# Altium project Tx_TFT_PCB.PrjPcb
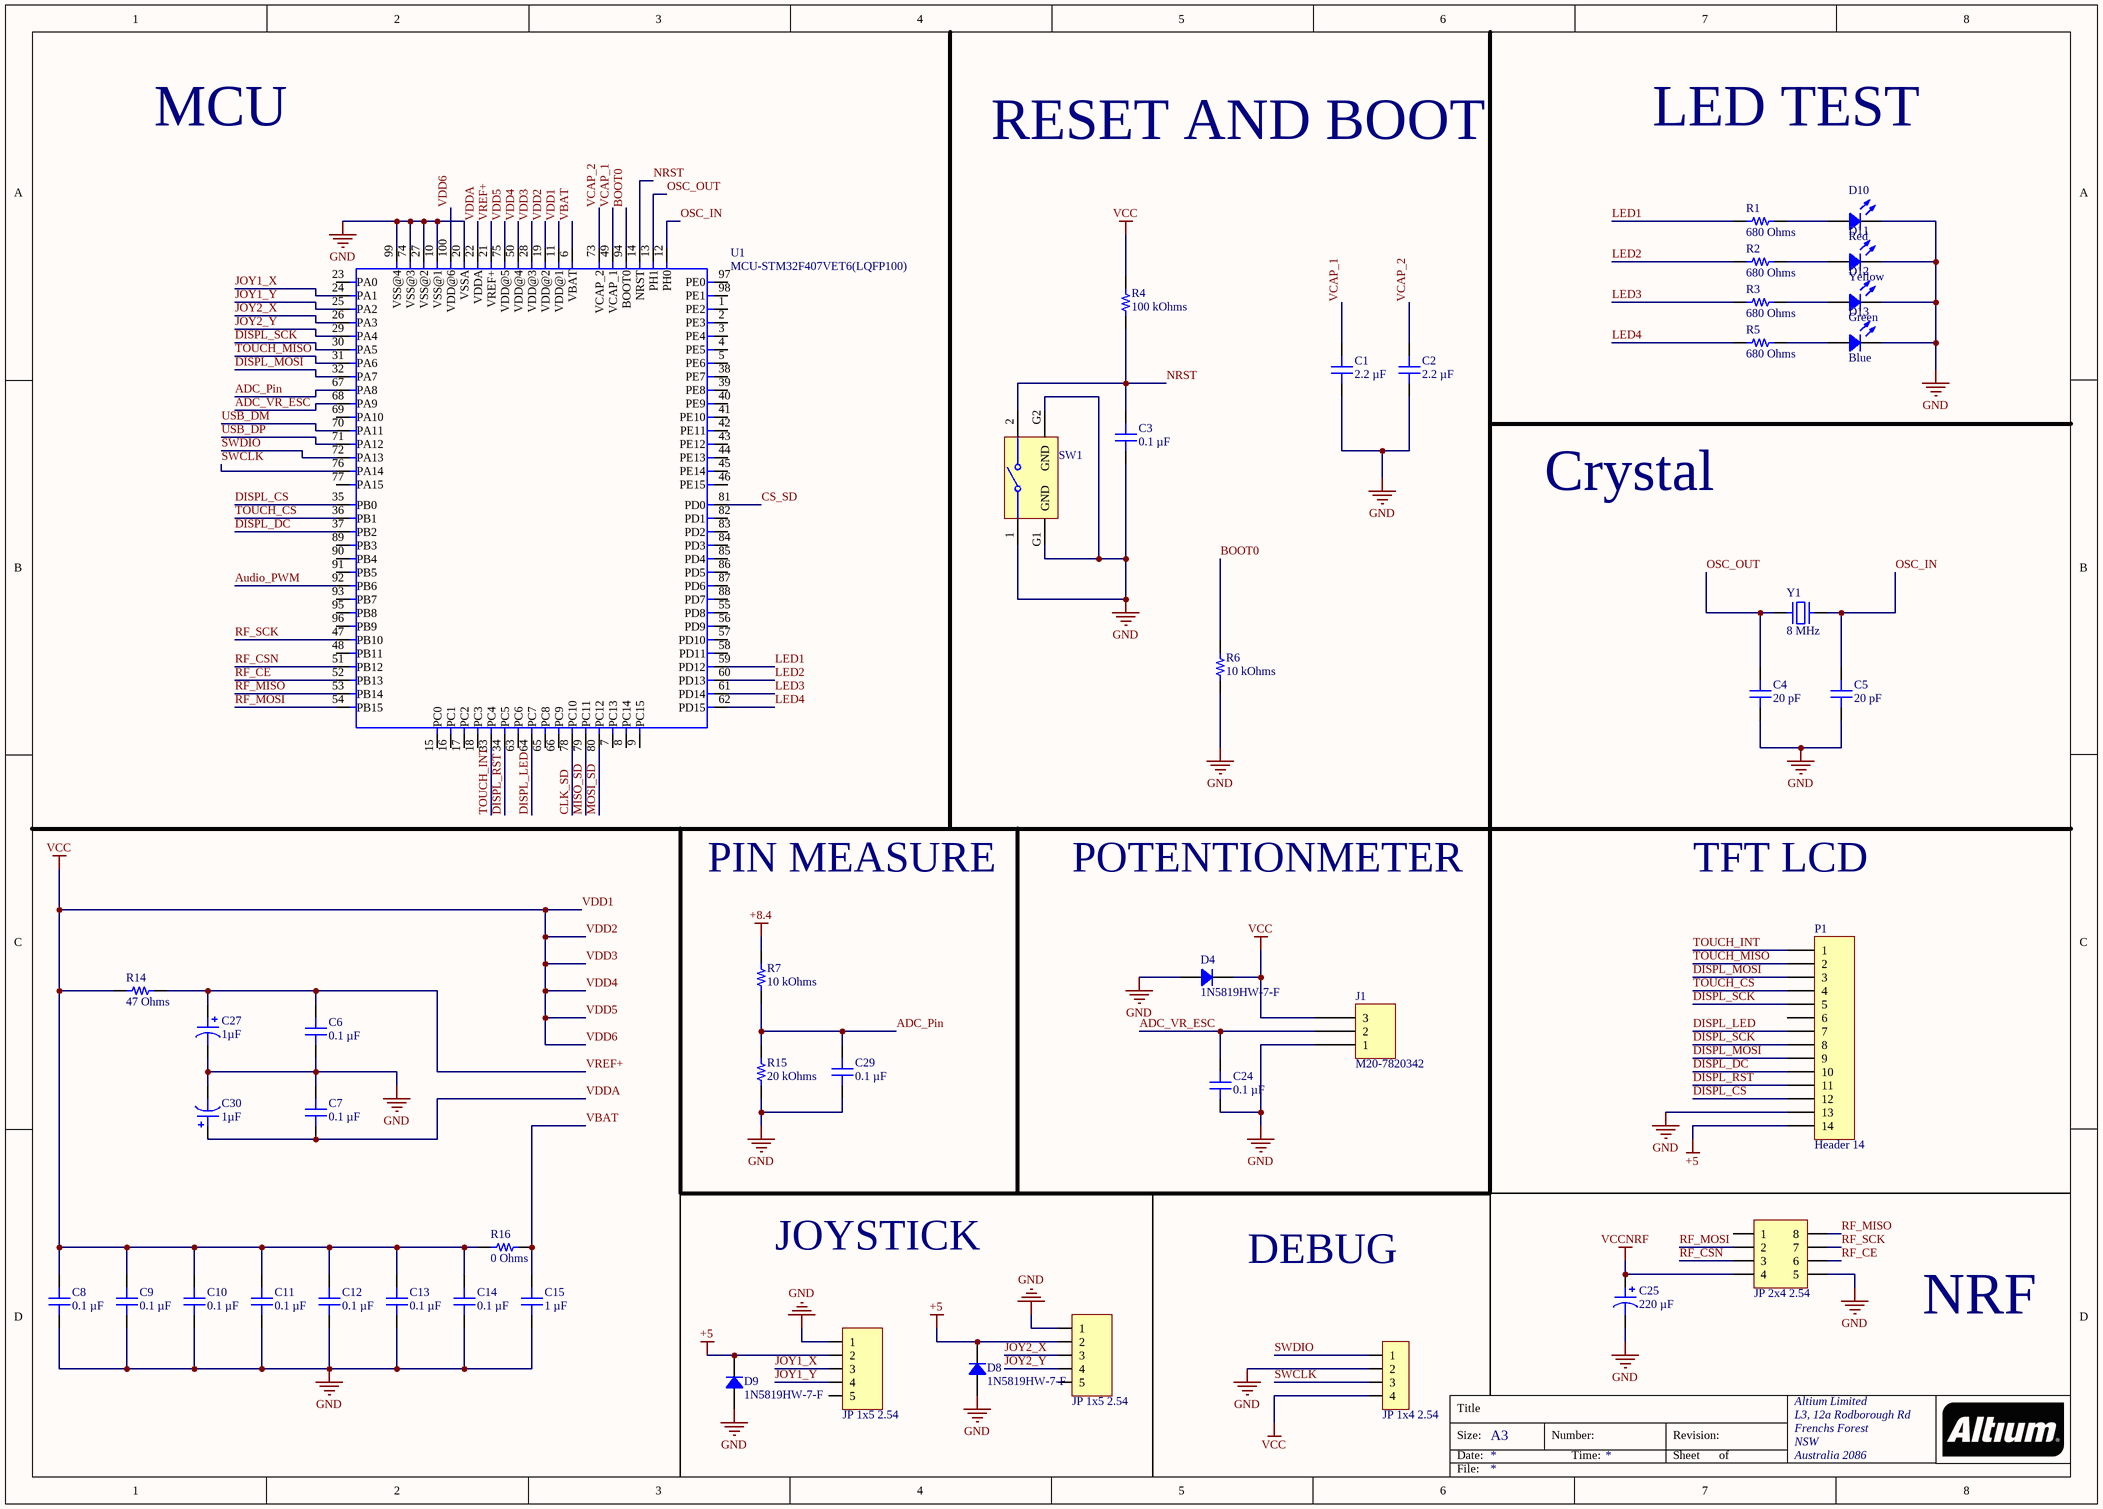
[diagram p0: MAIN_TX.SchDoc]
4 sheets, 123 parts. Net scope: global (net labels, ports and power ports of the same name join across sheets).
Board file: TX_PCB.PcbDoc
Sheets:
  MAIN_TX.SchDoc
  Audio.SchDoc
  Power_2.SchDoc
  USB_C.SchDoc

## Sheet MAIN_TX.SchDoc
size A3; Organization: Altium Limited; Address1: L3, 12a Rodborough Rd; Address2: Frenchs Forest; Address3: NSW; Address4: Australia 2086

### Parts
C1  2.2 µF  [CAP 0402_1005]
C2  2.2 µF  [CAP 0402_1005]
C3  0.1 µF  [CAP 0402_1005]
C4  20 pF  [CAP 0402_1005]
C5  20 pF  [CAP 0402_1005]
C6  0.1 µF  [CAP 0402_1005]
C7  0.1 µF  [CAP 0402_1005]
C8  0.1 µF  [CAP 0402_1005]
C9  0.1 µF  [CAP 0402_1005]
C10  0.1 µF  [CAP 0402_1005]
C11  0.1 µF  [CAP 0402_1005]
C12  0.1 µF  [CAP 0402_1005]
C13  0.1 µF  [CAP 0402_1005]
C14  0.1 µF  [CAP 0402_1005]
C15  1 µF  [CAP 0402_1005]
C24  0.1 µF  [CAP 0603_1608]
C25  220 µF  [CAP ALSMD 6.6MM H6.1MM]
C27  1µF  [CAP POL 1206_3216]
C29  0.1 µF  [CAP 0603_1608]
C30  1µF  [CAP POL 1206_3216]
D4  1N5819HW-7-F  [SOD-123]
D8  1N5819HW-7-F  [SOD-123]
D9  1N5819HW-7-F  [SOD-123]
D10  Red  [LED 0402_1005 RED]
D11  Yellow  [LED 0402_1005 YELLOW]
D12  Green  [LED 0402_1005 GREEN]
D13  Blue  [LED 0402_1005 BLUE]
J1  M20-7820342  [HARWIN M20-7820345]
JP1  JP 1x4 2.54  [JP 1x4 CC]
JP2  JP 2x4 2.54  [JP 2x4 CT]
JP3  JP 1x5 2.54  [JP 1x5 DT]
JP4  JP 1x5 2.54  [JP 1x5 DT]
P1  Header 14  [HDR1X14]
R1  680 Ohms  [RES 0402_1005]
R2  680 Ohms  [RES 0402_1005]
R3  680 Ohms  [RES 0402_1005]
R4  100 kOhms  [RES 0402_1005]
R5  680 Ohms  [RES 0402_1005]
R6  10 kOhms  [RES 0402_1005]
R7  10 kOhms  [RES 0402_1005]
R14  47 Ohms  [RES 0603_1608]
R15  20 kOhms  [RES 0603_1608]
R16  0 Ohms  [RES 0603_1608]
SW1  431256083716  [4312560837x6]  (value not drawn)
U1  MCU-STM32F407VET6(LQFP100)  [LQFP100-0.5-13.8X13.8MM]
Y1  8 MHz  [NDK NX5032GA]

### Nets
+5: D8.2 D9.2 JP3.2 JP4.2 P1.14
+8.4: R7.2
GND: C1.1 C2.1 C3.1 C4.1 C5.1 C6.1 C7.2 C8.1 C9.1 C10.1 C11.1 C12.1 C13.1 C14.1 C15.1 C24.1 C25.2 C27.2 C29.1 C30.2 D4.1 D8.1 D9.1 D10.2 D11.2 D12.2 D13.2 J1.1 JP1.2 JP2.5 JP3.1 JP4.1 P1.13 R6.1 R15.1 SW1.1 SW1.G1(GND) SW1.G2(GND) U1.10(VSS@1) U1.20(VSSA) U1.27(VSS@2) U1.74(VSS@3) U1.99(VSS@4)
VCCNRF: C25.1 JP2.4
VDD1: C8.2 C9.2 C10.2 C11.2 C12.2 C13.2 C14.2 D4.2 J1.3 JP1.4 R4.2 R14.1 R16.1 U1.11(VDD@1) U1.19(VDD@2) U1.28(VDD@3) U1.50(VDD@4) U1.75(VDD@5) U1.100(VDD@6)  [also labelled VCC, VDD2, VDD3, VDD4, VDD5, VDD6]
ADC_Pin: C29.2 R7.1 R15.2 U1.67(PA8)
ADC_VR_ESC: C24.2 J1.2 U1.68(PA9)
Audio_PWM: U1.92(PB6)
BOOT0: R6.2 U1.94(BOOT0)
CLK_SD: U1.78(PC10)
CS_SD: U1.81(PD0)
DISPL_CS: P1.12 U1.35(PB0)
DISPL_DC: P1.10 U1.37(PB2)
DISPL_LED: P1.7 U1.64(PC7)
DISPL_MOSI: P1.3 P1.9 U1.32(PA7)
DISPL_RST: P1.11 U1.34(PC5)
DISPL_SCK: P1.5 P1.8 U1.30(PA5)
JOY1_X: JP3.3 U1.24(PA1)
JOY1_Y: JP3.4 U1.25(PA2)
JOY2_X: JP4.3 U1.26(PA3)
JOY2_Y: JP4.4 U1.29(PA4)
LED1: R1.1 U1.59(PD12)
LED2: R2.1 U1.60(PD13)
LED3: R3.1 U1.61(PD14)
LED4: R5.1 U1.62(PD15)
MISO_SD: U1.79(PC11)
MOSI_SD: U1.80(PC12)
NRST: C3.2 R4.1 SW1.2 U1.14(NRST)
OSC_IN: C5.2 U1.12(PH0) Y1.2
OSC_OUT: C4.2 U1.13(PH1) Y1.1
RF_CE: JP2.6 U1.52(PB13)
RF_CSN: JP2.3 U1.51(PB12)
RF_MISO: JP2.8 U1.53(PB14)
RF_MOSI: JP2.2 U1.54(PB15)
RF_SCK: JP2.7 U1.47(PB10)
SWCLK: JP1.3 U1.76(PA14)
SWDIO: JP1.1 U1.72(PA13)
TOUCH_CS: P1.4 U1.36(PB1)
TOUCH_INT: P1.1 U1.33(PC4)
TOUCH_MISO: P1.2 U1.31(PA6)
USB_DM: U1.70(PA11)
USB_DP: U1.71(PA12)
VBAT: C15.2 R16.2 U1.6(VBAT)
VCAP_1: C1.2 U1.49(VCAP_1)
VCAP_2: C2.2 U1.73(VCAP_2)
VDDA: C7.1 C30.1 U1.22(VDDA)
VREF+: C6.2 C27.1 R14.2 U1.21(VREF+)
NetD10_1: D10.1 R1.2
NetD11_1: D11.1 R2.2
NetD12_1: D12.1 R3.2
NetD13_1: D13.1 R5.2

Not connected (* = marked no-connect by the designer): JP2 1; JP3 5; JP4 5; P1 6; U1 1(PE2) 2(PE3) 3(PE4) 4(PE5) 5(PE6) 7(PC13) 8(PC14) 9(PC15) 15(PC0) 16(PC1) 17(PC2) 18(PC3) 23(PA0) 38(PE7) 39(PE8) 40(PE9) 41(PE10) 42(PE11) 43(PE12) 44(PE13) 45(PE14) 46(PE15) 48(PB11) 55(PD8) 56(PD9) 57(PD10) 58(PD11) 63(PC6) 65(PC8) 66(PC9) 69(PA10) 77(PA15) 82(PD1) 83(PD2) 84(PD3) 85(PD4) 86(PD5) 87(PD6) 88(PD7) 89(PB3) 90(PB4) 91(PB5) 93(PB7) 95(PB8) 96(PB9) 97(PE0) 98(PE1)

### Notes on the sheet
- MCU
- RESET AND BOOT
- LED TEST
- Crystal
- PIN MEASURE
- POTENTIONMETER
- TFT LCD
- JOYSTICK
- DEBUG
- NRF

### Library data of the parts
C1 C2 = GRT155C81A225KE13D: CAP CER 2.2UF 10V X6S 0402; manufacturer: Murata Electronics; Tolerance: ±10%
C3 C6-C14 = KGM05AR51A104KN: CAP CER 0.1UF 10V X5R 0402; manufacturer: KYOCERA AVX; Tolerance: ±10%
C4 C5 = C0402C200K8GAC7867: CAP CER 20PF 10V NP0 0402; manufacturer: KEMET; Temperature Coefficient: C0G, NP0; Tolerance: ±10%
C15 = GRM155C71A105KE11D: CAP CER 1UF 10V X7S 0402; manufacturer: Murata Electronics; Tolerance: ±10%
C24 C29 = VJ0603Y104KXQCW1BC: CAP CER 0.1UF 10V X7R 0603; manufacturer: Vishay Vitramon; Tolerance: ±10%
C25 = UCM1A221MCL1GS: CAP ALUM 220UF 20% 10V SMD; manufacturer: Nichicon; Impedance: 260 mOhms; Lifetime @ Temp.: 2000 Hrs @ 105°C; Polarization: Polar; Ripple Current @ High Frequency: 300 mA @ 100 kHz; Ripple Current @ Low Frequency: 150 mA @ 120 Hz; Surface Mount Land Size: 0.260" L x 0.260" W (6.60mm x 6.60mm)
C27 C30 = TAJA105K016RNJ: CAP TANT 1UF 10% 16V 1206; manufacturer: AVX Corporation; Manufacturer Size Code: A; ESR (Equivalent Series Resistance): 11Ohm; Type: Molded
D4 D8 D9 = 1N5819HW-7-F: DIODE SCHOTTKY 40V 1A SOD123; Manufacturer: Diodes Incorporated; Capacitance @ Vr, F: 60pF @ 4V, 1MHz; Current - Reverse Leakage @ Vr: 1 mA @ 40 V; Speed: Fast Recovery =< 500ns, > 200mA (Io); Voltage - Forward (Vf) (Max) @ If: 450 mV @ 1 A
D10 = SM0402RC: LED RED CLEAR 0402 SMD; Manufacturer: Bivar Inc.; Configuration: 0402; Current - Test: 20mA; Lens Color: Colorless; Lens Size: 0.50mm x 1.00mm; Lens Style: Rectangle with Flat Top; Millicandela Rating: 90mcd; Viewing Angle: 130°; Voltage - Forward (Vf) (Typ): 2.1V; Wavelength - Dominant: 631nm; Wavelength - Peak: 645nm
D11 = IN-S42ATY: LED YELLOW CLEAR 0402 SMD; Manufacturer: Inolux; Configuration: Standard; Current - Test: 20mA; Lens Size: 0.60mm x 0.45mm; Lens Style: Rectangle with Flat Top; Millicandela Rating: 145mcd; Viewing Angle: 130°; Voltage - Forward (Vf) (Typ): 1.9V; Wavelength - Dominant: 592nm; Wavelength - Peak: 593nm
D12 = APG1005ZGC-5MAV: LED GREEN CLEAR 0402 SMD; Manufacturer: Kingbright; Configuration: Standard; Current - Test: 5mA; Lens Color: Colorless; Lens Size: 0.60mm x 0.50mm; Lens Style: Rectangle with Flat Top; Millicandela Rating: 280mcd; Viewing Angle: 140°; Voltage - Forward (Vf) (Typ): 2.85V; Wavelength - Dominant: 525nm; Wavelength - Peak: 515nm
D13 = XZBBR68W5MAV-3: LED BLUE CLEAR 0402 SMD; Manufacturer: SunLED; Configuration: Standard; Current - Test: 5mA; Lens Color: Colorless; Lens Size: 0.60mm x 0.50mm; Lens Style: Rectangle with Flat Top; Millicandela Rating: 27mcd; Viewing Angle: 140°; Voltage - Forward (Vf) (Typ): 2.9V; Wavelength - Dominant: 467nm; Wavelength - Peak: 461nm
J1 = M20-7820342: CONN RCPT 3POS 0.1 GOLD PCB; Manufacturer: Harwin Inc.; Connector Type: Receptacle; Contact Length - Post: 0.118" (3.00mm); Current Rating (Amps): 3A; Mated Stacking Heights: 11.04mm, 12.63mm; Material Flammability Rating: UL94 V-0; Number of Positions: 3; Number of Positions Loaded: All; Pitch - Mating: 0.100" (2.54mm); Style: Board to Board or Cable
JP1 = JP 1x4 2.54 Cai Cong: Cắm; Ten_Linh_Kien: Jump Đơn Cái 2.54MM 1x40P Cong; Don_Vi: Con; Ma_Hang: MH001265
JP2 = JP 2x4 2.54 Cai Thang: Cắm; Ten_Linh_Kien: Jump Đôi Cái 2.54MM 2x20P Thẳng; Don_Vi: Con; Ma_Hang: MH008647
JP3 JP4 = JP 1x5 2.54 Duc Thang: Cắm; Ten_Linh_Kien: Jump Đơn Đực 2.54MM 1x40P Thẳng 11MM; Don_Vi: Con; Ma_Hang: MH000903
P1 = Header 14: Header, 14-Pin
R1-R3 R5 = RC0402FR-07680RL: RES 680 OHM 1% 1/16W 0402; Manufacturer: Yageo; Power (Watts): 0.063W, 1/16W; Temperature Coefficient: ±100ppm/°C
R4 = MCS04020D1003BE100: RES SMD 100K OHM 0.1% 1/16W 0402; Manufacturer: Vishay Beyschlag; Power (Watts): 0.063W, 1/16W; Temperature Coefficient: ±25ppm/°C
R6 R7 = RP73PF1E10KBTD: RES 10K OHM 0.1% 1/10W 0402; Manufacturer: TE Connectivity Passive Product; Power (Watts): 0.1W, 1/10W; Temperature Coefficient: ±25ppm/°C
R14 = CRT0603-FY-47R0ELF: RES SMD 47 OHM 1% 1/10W 0603; Manufacturer: Bourns Inc.; Power (Watts): 0.1W, 1/10W; Temperature Coefficient: ±25ppm/°C
R15 = RG1608P-203-B-T5: RES SMD 20K OHM 0.1% 1/10W 0603; Manufacturer: Susumu; Power (Watts): 0.1W, 1/10W; Temperature Coefficient: ±25ppm/°C
R16 = CR0603AJ/-000ELF: RES 0 OHM JUMPER 1/10W 0603; Manufacturer: Bourns Inc.; Power (Watts): 0.1W, 1/10W
SW1 = 431256083716: WS-TATU THT Tact Switch 6x6mm Right Angled Type with ground terminal, SPST-NO, 12VDC, 50mA, 160g; Manufacturer: Wurth Elektronik; Washable: No
U1 = MCU-STM32F407VET6(LQFP100): ARMÂ® CortexÂ®-M4 STM32F4 Microcontroller IC 32-Bit Single-Core 168MHz 512KB (512K x 8) FLASH 100-LQFP (14x14); MF: STMicroelectronics
Y1 = NX5032GA-8.000M-STD-CSU-1: CRYSTAL 8.0000MHZ 8PF SMD; Manufacturer: NDK America, Inc.; ESR (Equivalent Series Resistance): 300 Ohms; Frequency Stability: ±150ppm; Frequency Tolerance: ±50ppm; Operating Mode: Fundamental

## Sheet Audio.SchDoc
size A4; Organization: Altium Limited; Address1: L3, 12a Rodborough Rd; Address2: Frenchs Forest; Address3: NSW; Address4: Australia 2086
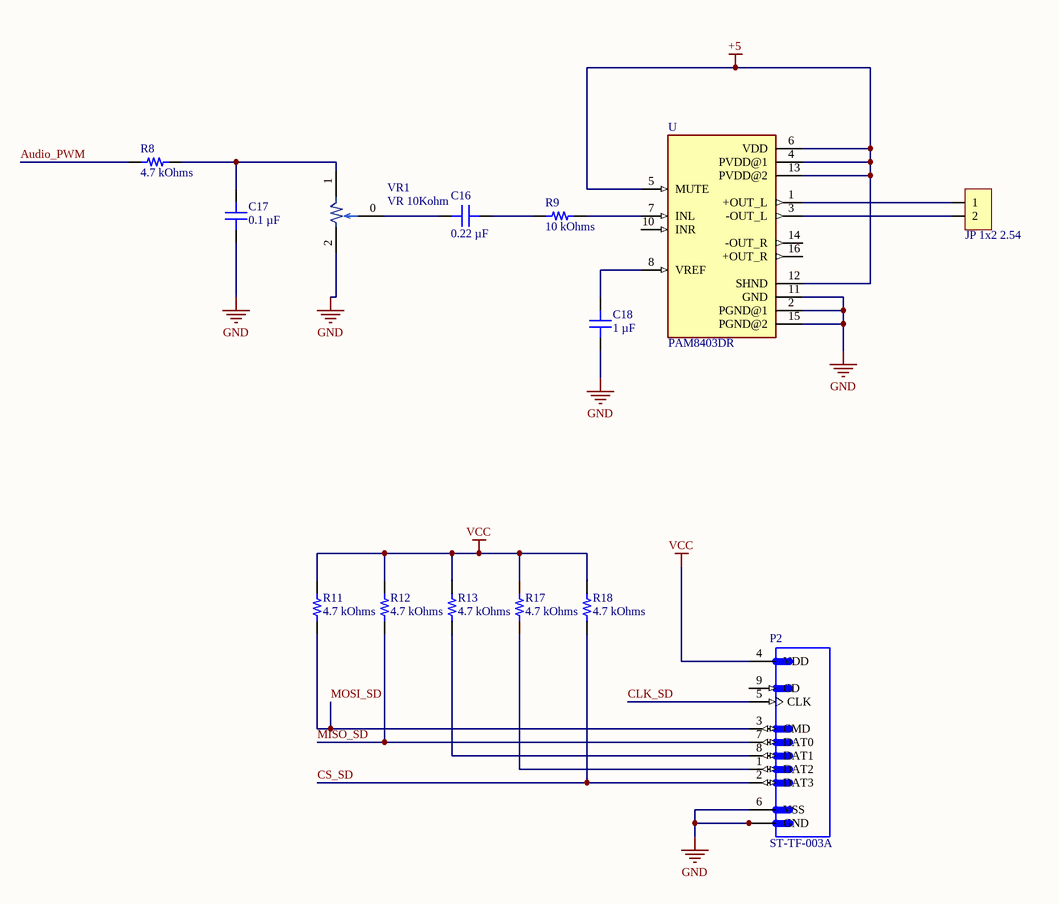
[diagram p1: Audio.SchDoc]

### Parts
C16  0.22 µF  [CAP 0402_1005]
C17  0.1 µF  [CAP 0402_1005]
C18  1 µF  [CAP 0402_1005]
JP5  JP 1x2 2.54  [JP 1x2 CT]
P2  ST-TF-003A  [SUNTECH_ST-TF-003A]
R8  4.7 kOhms  [RES 0402_1005]
R9  10 kOhms  [RES 0402_1005]
R11  4.7 kOhms  [RES 0402_1005]
R12  4.7 kOhms  [RES 0402_1005]
R13  4.7 kOhms  [RES 0402_1005]
R17  4.7 kOhms  [RES 0402_1005]
R18  4.7 kOhms  [RES 0402_1005]
U  PAM8403DR  [SOIC127P605X150-16N]
VR1  VR 10Kohm  [VR 10kohm]

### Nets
+5: U.4(PVDD@1) U.5(MUTE) U.6(VDD) U.12(SHND) U.13(PVDD@2)
GND: C17.1 C18.1 P2.6(VSS) P2.G1(GND) P2.G2(GND) P2.G3(GND) P2.G4(GND) U.2(PGND@1) U.11(GND) U.15(PGND@2) VR1.2
VCC: P2.4(VDD) R11.2 R12.2 R13.2 R17.2 R18.2  [project net VDD1]
Audio_PWM: R8.2
CLK_SD: P2.5(CLK)
CS_SD: P2.2(DAT3) R18.1
MISO_SD: P2.7(DAT0) R12.1
MOSI_SD: P2.3(CMD) R11.1
NetC16_1: C16.1 VR1.0
NetC16_2: C16.2 R9.1
NetC17_2: C17.2 R8.1 VR1.1
NetC18_2: C18.2 U.8(VREF)
NetJP5_1: JP5.1 U.1(+OUT_L)
NetJP5_2: JP5.2 U.3(-OUT_L)
NetP2_1: P2.1(DAT2) R17.1
NetP2_8: P2.8(DAT1) R13.1
NetR9_2: R9.2 U.7(INL)

Not connected (* = marked no-connect by the designer): P2 9(CD); U 10(INR) 14(-OUT_R) 16(+OUT_R)

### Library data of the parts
C16 = 0402X224K100CT: CAP CER 0.22UF 10V X5R 0402; manufacturer: Walsin Technology Corporation; Tolerance: ±10%
C17 = CGA2B2X5R1A104M050BA: CAP CER 0.1UF 10V X5R 0402; manufacturer: TDK Corporation; Tolerance: ±20%
C18 = C0402C105K8PAC7867: CAP CER 1UF 10V X5R 0402; manufacturer: KEMET; Tolerance: ±10%
JP5 = JP 1x2 2.54 Cai Thang: Cắm; Ten_Linh_Kien: Jump Đơn Cái 2.54MM 1x20P Thẳng; Don_Vi: Con; Ma_Hang: MH004006
P2 = ST-TF-003A: Micro SD Card Socket
R8 R11-R13 R17 R18 = RK73H1ERTTP4701F: RES 4.7K OHM 1% 1/10W 0402; Manufacturer: KOA Speer Electronics, Inc.; Power (Watts): 0.1W, 1/10W; Temperature Coefficient: ±100ppm/°C
R9 = MCS0402MC1002FE000: RES SMD 10K OHM 1% 1/10W 0402; Manufacturer: Vishay Beyschlag; Power (Watts): 0.1W, 1/10W; Temperature Coefficient: ±50ppm/°C
U = PAM8403DR: Amplifier IC 2-Channel _Stereo_ Class D 16-SOP; MF: Diodes Inc.

## Sheet Power_2.SchDoc
size A4; Organization: Altium Limited; Address1: L3, 12a Rodborough Rd; Address2: Frenchs Forest; Address3: NSW; Address4: Australia 2086
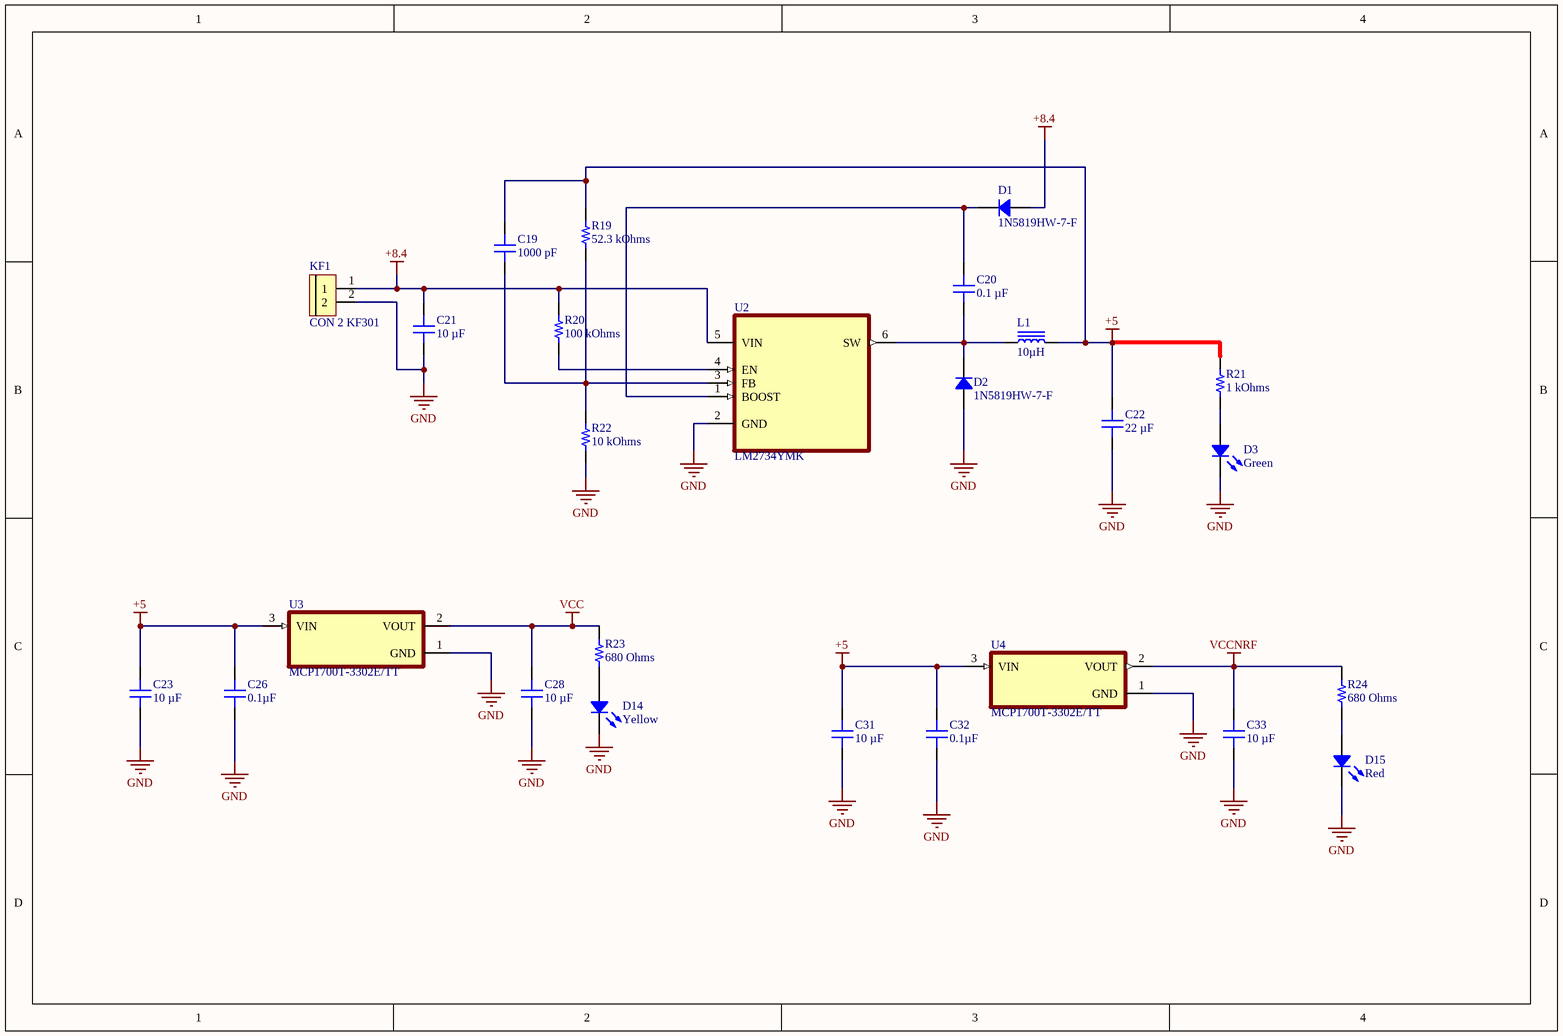
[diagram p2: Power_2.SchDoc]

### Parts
C19  1000 pF  [CAP 0402_1005]
C20  0.1 µF  [CAP 0402_1005]
C21  10 µF  [CAP 1210_3225 - 1MM]
C22  22 µF  [CAP 1210_3225 - 1MM]
C23  10 µF  [CAP 1210_3225 - 1MM]
C26  0.1µF  [CAP 0402_1005]
C28  10 µF  [CAP 1210_3225 - 1MM]
C31  10 µF  [CAP 1210_3225 - 1MM]
C32  0.1µF  [CAP 0402_1005]
C33  10 µF  [CAP 1210_3225 - 1MM]
D1  1N5819HW-7-F  [SOD-123]
D2  1N5819HW-7-F  [SOD-123]
D3  Green  [LED 0402_1005 GREEN]
D14  Yellow  [LED 0402_1005 YELLOW]
D15  Red  [LED 0402_1005 RED]
KF1  CON 2 KF301  [Con 2 KF301 5.08]
L1  10µH  [TDK SLF7032]
R19  52.3 kOhms  [RES 0402_1005]
R20  100 kOhms  [RES 0402_1005]
R21  1 kOhms  [RES 0402_1005]
R22  10 kOhms  [RES 0402_1005]
R23  680 Ohms  [RES 0402_1005]
R24  680 Ohms  [RES 0402_1005]
U2  LM2734YMK  [SOT95P285X100-6N]
U3  MCP1700T-3302E/TT  [SOT95P237X112-3N]
U4  MCP1700T-3302E/TT  [SOT95P237X112-3N]

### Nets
+5: C19.2 C22.2 C23.2 C26.2 C31.2 C32.2 L1.2 R19.2 R21.2 U3.3(VIN) U4.3(VIN)
+8.4: C21.2 D1.1 KF1.1 R20.2 U2.5(VIN)
GND: C21.1 C22.1 C23.1 C26.1 C28.1 C31.1 C32.1 C33.1 D2.1 D3.2 D14.2 D15.2 KF1.2 R22.1 U2.2(GND) U3.1(GND) U4.1(GND)
VCC: C28.2 R23.2 U3.2(VOUT)  [project net VDD1]
VCCNRF: C33.2 R24.2 U4.2(VOUT)
NetC19_1: C19.1 R19.1 R22.2 U2.3(FB)
NetC20_1: C20.1 D2.2 L1.1 U2.6(SW)
NetC20_2: C20.2 D1.2 U2.1(BOOST)
NetD3_1: D3.1 R21.1
NetD14_1: D14.1 R23.1
NetD15_1: D15.1 R24.1
NetR20_1: R20.1 U2.4(EN)

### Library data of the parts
C19 = LMF105B7102MVHF: CAP CER 1000PF 10V X7R 0402; manufacturer: Taiyo Yuden; Tolerance: ±20%
C20 = KGM05AR51A104KN: as C3 on sheet MAIN_TX
C21 C23 C28 C31 C33 = CGA6P3X8R1C106M250AB: CAP CER 10UF 16V X8R 1210; manufacturer: TDK Corporation; Tolerance: ±20%
C22 = C1210C226K4RAC7800: CAP CER 22UF 16V X7R 1210; manufacturer: KEMET; Tolerance: ±10%
C26 C32 = 0402ZC104KAT2A: CAP CER 0.1UF 10V X7R 0402; manufacturer: AVX Corporation; Tolerance: ±10%
D1 D2 = 1N5819HW-7-F: as D4 on sheet MAIN_TX
D3 = QBLP595-AG15-2897: LED GREEN CLEAR 0402 SMD; Manufacturer: QT Brightek (QTB); Configuration: Standard; Current - Test: 5mA; Lens Color: Colorless; Lens Size: 0.70mm x 0.50mm; Lens Style: Rectangle with Flat Top; Millicandela Rating: 16.5mcd; Viewing Angle: 140°; Voltage - Forward (Vf) (Typ): 1.9V; Wavelength - Dominant: 570nm
D14 = IN-S42BT5Y: LED YELLOW CLEAR 0402 SMD; Manufacturer: Inolux; Configuration: 0402; Current - Test: 5mA; Lens Color: 0.50mm; Lens Size: 0.70mm x 0.50mm; Lens Style: Rectangle with Flat Top; Millicandela Rating: 23mcd; Viewing Angle: 120°; Voltage - Forward (Vf) (Typ): 2V; Wavelength - Dominant: 585nm; Wavelength - Peak: 592nm
D15 = QBLP595-R5: LED RED CLEAR 0402 SMD; Manufacturer: QT Brightek (QTB); Configuration: Standard; Current - Test: 5mA; Lens Color: Colorless; Lens Size: 0.70mm x 0.50mm; Lens Style: Rectangle with Flat Top; Millicandela Rating: 31.5mcd; Viewing Angle: 140°; Voltage - Forward (Vf) (Typ): 1.85V; Wavelength - Dominant: 620nm
KF1 = CON 2 KF301: Cắm; Ma_Hang: MH000987; Ten_Linh_Kien: CON 2 KF301-2P 5.08MM Xanh Dương
L1 = SLF7032T-100M1R4-2PF: FIXED IND 10UH 1.4A 63.6 MOHM; Manufacturer: TDK Corporation; DC Resistance (DCR): 63.6mOhm Max; Inductance Frequency - Test: 100kHz; Material - Core: Ferrite; Shielding: Shielded; Tolerance: ±20%; Type: Wirewound
R19 = ERJ-2RKF5232X: RES SMD 52.3K OHM 1% 1/10W 0402; Manufacturer: Panasonic Electronic Components; Power (Watts): 0.1W, 1/10W; Temperature Coefficient: ±100ppm/°C
R20 = RP73PF1E100KBTD: RES 100K OHM 0.1% 1/10W 0402; Manufacturer: TE Connectivity Passive Product; Power (Watts): 0.1W, 1/10W; Temperature Coefficient: ±25ppm/°C
R21 = MCS0402MC1001FE000: RES SMD 1K OHM 1% 1/10W 0402; Manufacturer: Vishay Beyschlag; Power (Watts): 0.1W, 1/10W; Temperature Coefficient: ±50ppm/°C
R22 = MCS0402MC1002FE000: as R9 on sheet Audio
R23 R24 = RC0402FR-07680RL: as R1 on sheet MAIN_TX
U2 = LM2734YMK: Buck Switching Regulator IC Positive Adjustable 0.8V 1 Output 1A SOT-23-6 Thin, TSOT-23-6; MF: Texas Instruments
U3 U4 = MCP1700T-3302E/TT: Linear Voltage Regulator IC 1 Output 250mA SOT-23-3; MF: Microchip

## Sheet USB_C.SchDoc
size A3; Organization: Altium Limited; Address1: L3, 12a Rodborough Rd; Address2: Frenchs Forest; Address3: NSW; Address4: Australia 2086
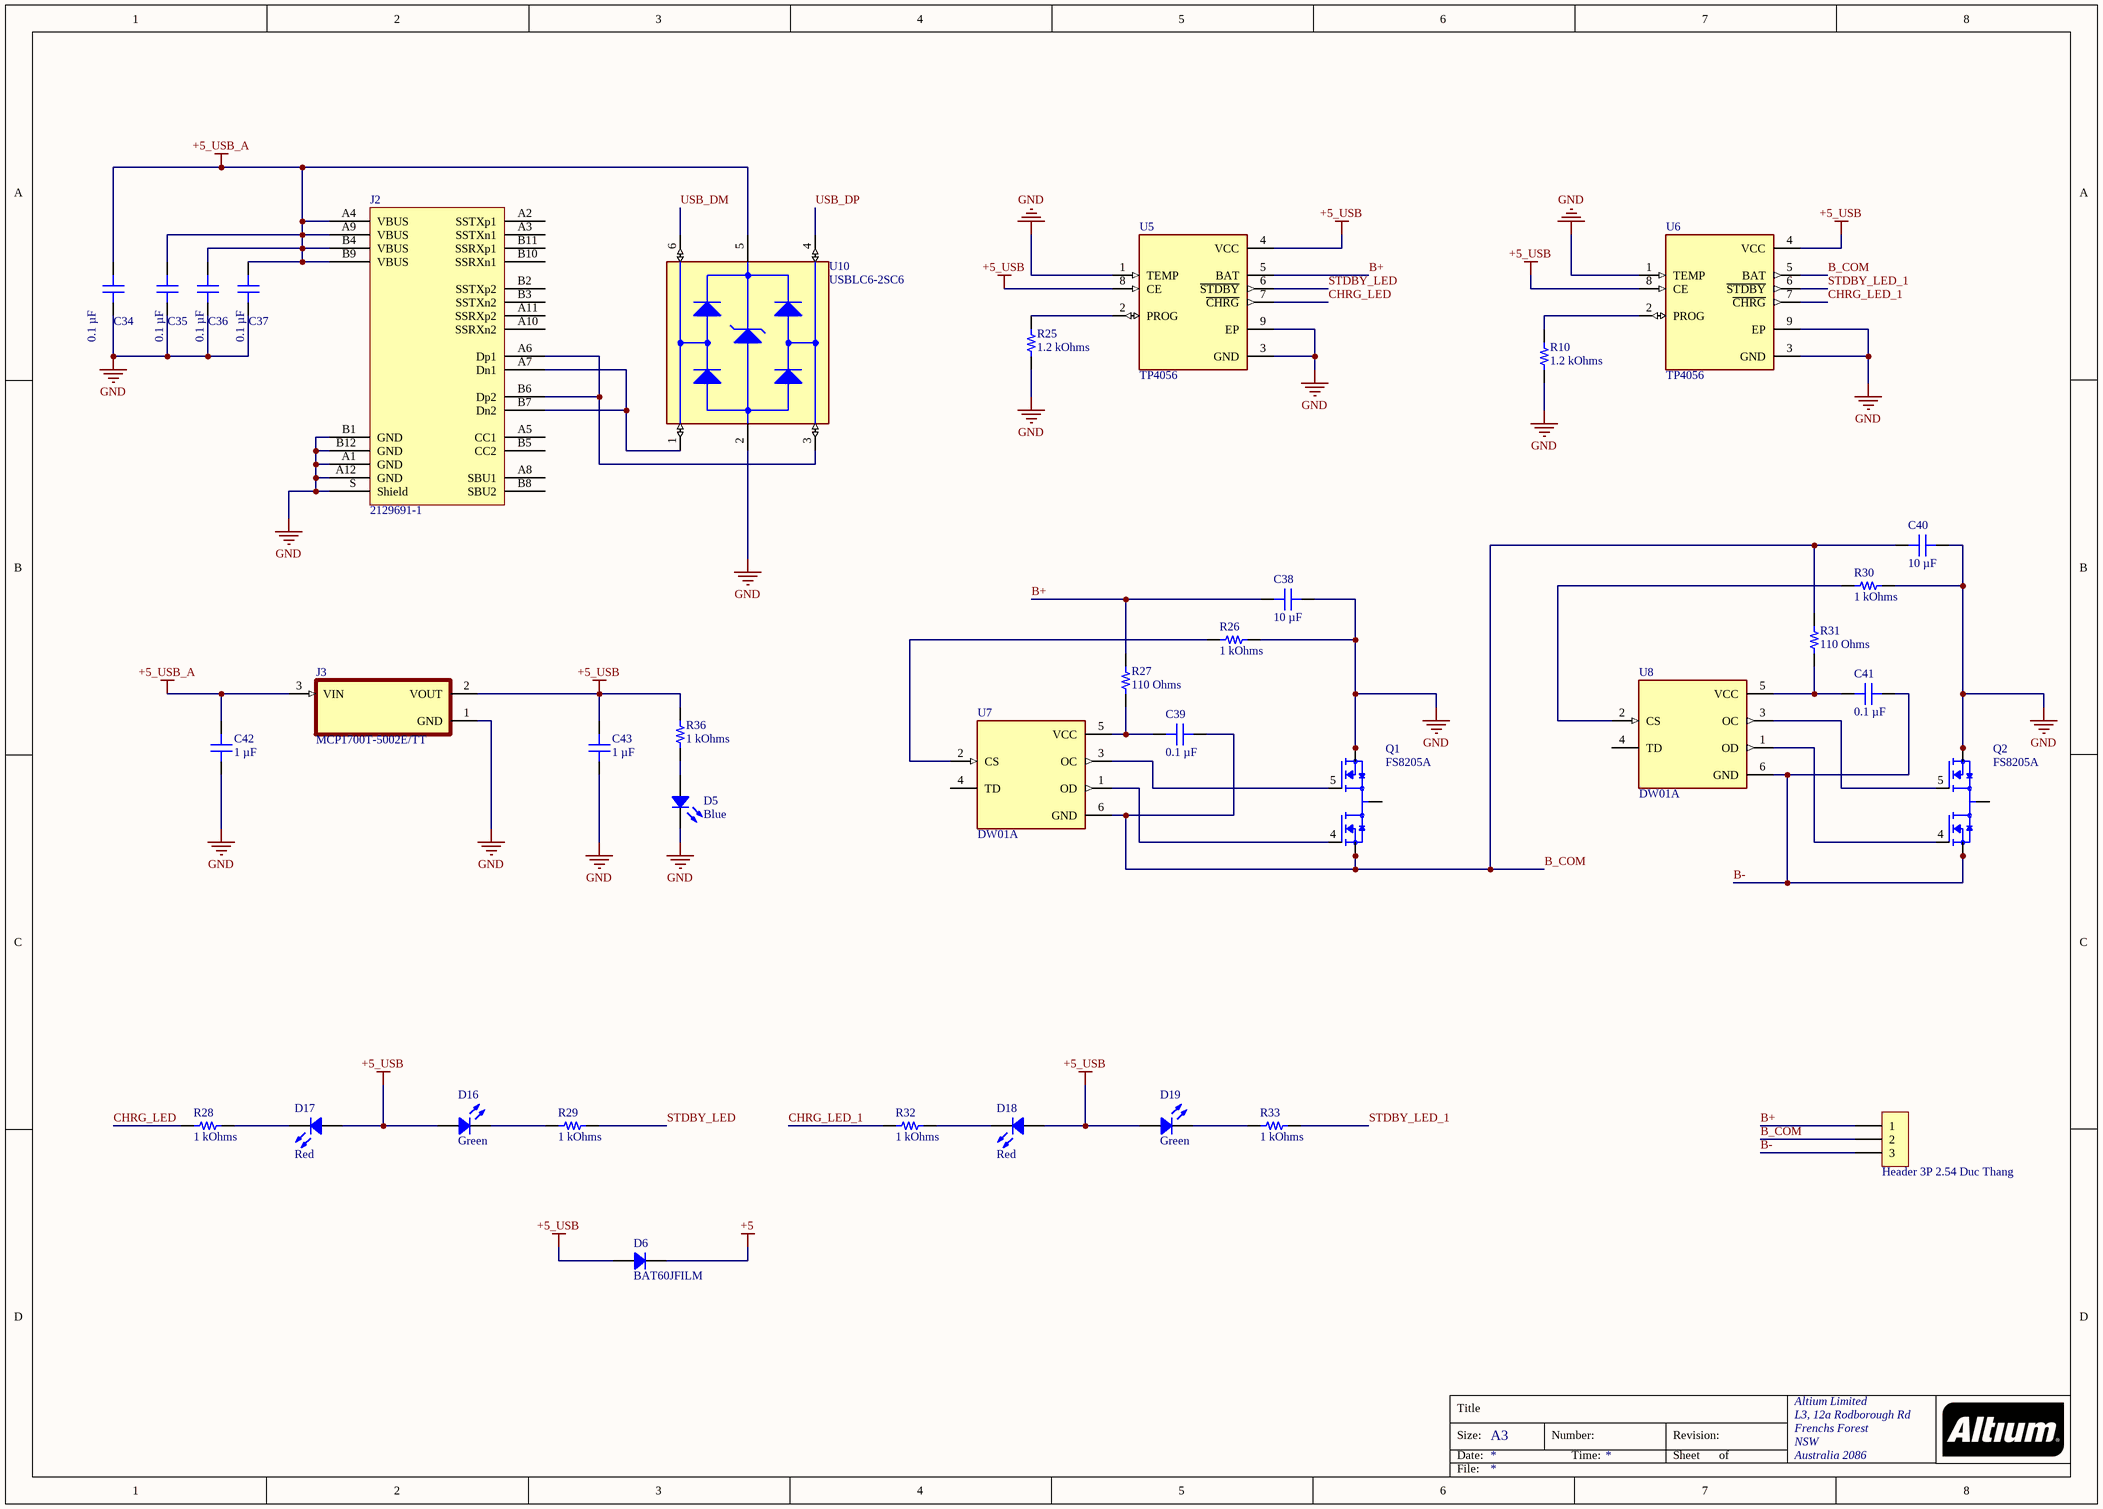
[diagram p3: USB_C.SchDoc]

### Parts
C34  0.1 µF  [CAP 0402_1005]
C35  0.1 µF  [CAP 0402_1005]
C36  0.1 µF  [CAP 0402_1005]
C37  0.1 µF  [CAP 0402_1005]
C38  10 µF  [CAP 0402_1005]
C39  0.1 µF  [CAP 0402_1005]
C40  10 µF  [CAP 0402_1005]
C41  0.1 µF  [CAP 0402_1005]
C42  1 µF  [CAP 0402_1005]
C43  1 µF  [CAP 0402_1005]
D5  Blue  [LED 0603_1608 BLUE]
D6  BAT60JFILM  [SOD323]
D16  Green  [LED 0402_1005 GREEN]
D17  Red  [LED 0402_1005 RED]
D18  Red  [LED 0402_1005 RED]
D19  Green  [LED 0402_1005 GREEN]
H1  Header 3P 2.54 Duc Thang  [XH2.54M-3]
J2  2129691-1  [TE USB-C 2129691-1]
J3  MCP1700T-5002E/TT  [SOT95P237X112-3N]
Q1  FS8205A  [SOP65P640X120-8N]
Q2  FS8205A  [SOP65P640X120-8N]
R10  1.2 kOhms  [RES 0402_1005]
R25  1.2 kOhms  [RES 0402_1005]
R26  1 kOhms  [RES 0402_1005]
R27  110 Ohms  [RES 0402_1005]
R28  1 kOhms  [RES 0402_1005]
R29  1 kOhms  [RES 0402_1005]
R30  1 kOhms  [RES 0402_1005]
R31  110 Ohms  [RES 0402_1005]
R32  1 kOhms  [RES 0402_1005]
R33  1 kOhms  [RES 0402_1005]
R36  1 kOhms  [RES 0402_1005]
U5  TP4056  [SOP127P600X175-9N]
U6  TP4056  [SOP127P600X175-9N]
U7  DW01A  [SOT95P280X145-6N]
U8  DW01A  [SOT95P280X145-6N]
U10  USBLC6-2SC6  [SOT95P280X145-6N]

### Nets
+5: D6.2
+5_USB: C43.1 D6.1 D16.1 D17.1 D18.1 D19.1 J3.2(VOUT) R36.2 U5.4(VCC) U5.8(CE) U6.4(VCC) U6.8(CE)
+5_USB_A: C34.1 C35.1 C36.1 C37.1 C42.2 J2.A4(VBUS) J2.A9(VBUS) J2.B4(VBUS) J2.B9(VBUS) J3.3(VIN) U10.5(VBUS)
GND: C34.2 C35.2 C36.2 C37.2 C38.2 C40.2 C42.1 C43.2 D5.2 J2.A1(GND) J2.A12(GND) J2.B1(GND) J2.B12(GND) J2.S(Shield) J3.1(GND) Q1.6(S2) Q1.7(S2) Q2.6(S2) Q2.7(S2) R10.1 R25.1 R26.2 R30.2 U5.1(TEMP) U5.3(GND) U5.9(EP) U6.1(TEMP) U6.3(GND) U6.9(EP) U10.2(GND)
B+: C38.1 H1.1 R27.2 U5.5(BAT)
B-: C41.2 H1.3 Q2.2(S1) Q2.3(S1) U8.6(GND)
B_COM: C39.2 C40.1 H1.2 Q1.2(S1) Q1.3(S1) R31.2 U6.5(BAT) U7.6(GND)
CHRG_LED: R28.1 U5.7(~{CHRG})
CHRG_LED_1: R32.1 U6.7(~{CHRG})
STDBY_LED: R29.2 U5.6(~{STDBY})
STDBY_LED_1: R33.2 U6.6(~{STDBY})
USB_DM: U10.6(I/O1_OUT)
USB_DP: U10.4(I/O2_OUT)
NetC39_1: C39.1 R27.1 U7.5(VCC)
NetC41_1: C41.1 R31.1 U8.5(VCC)
NetD5_1: D5.1 R36.1
NetD16_2: D16.2 R29.1
NetD17_2: D17.2 R28.2
NetD18_2: D18.2 R32.2
NetD19_2: D19.2 R33.1
NetJ2_A6: J2.A6(Dp1) J2.B6(Dp2) U10.3(I/O2_IN)
NetJ2_A7: J2.A7(Dn1) J2.B7(Dn2) U10.1(I/O1_IN)
NetQ1_1: Q1.1(D12) Q1.8(D12)
NetQ1_4: Q1.4(G1) U7.1(OD)
NetQ1_5: Q1.5(G2) U7.3(OC)
NetQ2_1: Q2.1(D12) Q2.8(D12)
NetQ2_4: Q2.4(G1) U8.1(OD)
NetQ2_5: Q2.5(G2) U8.3(OC)
NetR10_2: R10.2 U6.2(PROG)
NetR25_2: R25.2 U5.2(PROG)
NetR26_1: R26.1 U7.2(CS)
NetR30_1: R30.1 U8.2(CS)

Not connected (* = marked no-connect by the designer): J2 A2(SSTXp1) A3(SSTXn1) A5(CC1) A8(SBU1) A10(SSRXn2) A11(SSRXp2) B2(SSTXp2) B3(SSTXn2) B5(CC2) B8(SBU2) B10(SSRXn1) B11(SSRXp1); U7 4(TD); U8 4(TD)

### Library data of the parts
C34-C37 C39 = KGM05AR71A104KH: CAP CER 0.1UF 10V X7R 0402; manufacturer: KYOCERA AVX; Tolerance: ±10%
C38 C40 = CL05A106MP8NUB8: CAP CER 10UF 10V X5R 0402; manufacturer: Samsung Electro-Mechanics; Tolerance: ±20%
C41 = KGM05AV51A104ZH: CAP CER 0.1UF 10V Y5V 0402; manufacturer: KYOCERA AVX; Temperature Coefficient: Y5V (F); Tolerance: -20%, +80%
C42 C43 = KGM05AR51A105KH: CAP CER 1UF 10V X5R 0402; manufacturer: KYOCERA AVX; Tolerance: ±10%
D5 = 150060BS75000: LED BLUE CLEAR 0603 SMD; Manufacturer: Würth Elektronik; Configuration: Standard; Current - Test: 20mA; Lens Color: Colorless; Lens Size: 1.10mm x 0.70mm; Lens Style: Rectangle with Flat Top; Millicandela Rating: 145mcd; Viewing Angle: 140°; Voltage - Forward (Vf) (Typ): 3.2V; Wavelength - Dominant: 470nm; Wavelength - Peak: 465nm
D6 = BAT60JFILM: DIODE SCHOTTKY 10V 3A SOD323; Manufacturer: STMicroelectronics; Current - Reverse Leakage @ Vr: 6 µA @ 10 V; Speed: Fast Recovery =< 500ns, > 200mA (Io); Voltage - Forward (Vf) (Max) @ If: 580 mV @ 1 A
D16 D19 = 150040GS73240: LED GREEN CLEAR 0402 SMD; Manufacturer: Würth Elektronik; Configuration: Standard; Current - Test: 20mA; Lens Color: Colorless; Lens Size: 1.00mm x 0.50mm; Lens Style: Rectangle with Flat Top; Millicandela Rating: 800mcd; Viewing Angle: 120°; Voltage - Forward (Vf) (Typ): 3.2V; Wavelength - Dominant: 525nm; Wavelength - Peak: 515nm
D17 D18 = 150040SS73220: LED RED CLEAR 0402 SMD; Manufacturer: Würth Elektronik; Configuration: 0402; Current - Test: 20mA; Lens Color: Colorless; Lens Size: 1.00mm x 0.50mm; Lens Style: Rectangle with Flat Top; Millicandela Rating: 90mcd; Viewing Angle: 120°; Voltage - Forward (Vf) (Typ): 2V; Wavelength - Dominant: 630nm; Wavelength - Peak: 645nm
H1 = Header 3P 2.54 Duc Thang: Cắm; Ten_Linh_Kien: Header 3P XH2.54-3P Đực Thẳng; Don_Vi: Con; Ma_Hang: MH001292
J2 = 2129691-1: CONN RCPT USB3.1 TYPEC 24POS SMD; Manufacturer: TE Connectivity AMP Connectors; Connector Type: USB - C (Type - C); Current Rating (Amps): 0.25A, 1.25A, 5A; Gender: Receptacle; Mating Cycles: 10000; Number of Contacts: 24; Number of Ports: 1; Specifications: USB 3.1 (USB 3.1 Gen 2, Superspeed+); Voltage - Rated: 30V
Q1 Q2 = FS8205A: N/A; MF: Fortune Semiconductor
R10 = MCS04020C1201FE000: RES SMD 1.2K OHM 1% 1/10W 0402; Manufacturer: Vishay Beyschlag; Power (Watts): 0.1W, 1/10W; Temperature Coefficient: ±50ppm/°C
R25 = ERJ-2RKF1201X: RES SMD 1.2K OHM 1% 1/10W 0402; Manufacturer: Panasonic Electronic Components; Power (Watts): 0.1W, 1/10W; Temperature Coefficient: ±100ppm/°C
R26 = RK73H1ERTTP1001F: RES 1K OHM 1% 1/10W 0402; Manufacturer: KOA Speer Electronics, Inc.; Power (Watts): 0.1W, 1/10W; Temperature Coefficient: ±100ppm/°C
R27 = RK73H1ETTP1100F: RES 110 OHM 1% 1/10W 0402; Manufacturer: KOA Speer Electronics, Inc.; Power (Watts): 0.1W, 1/10W; Temperature Coefficient: ±100ppm/°C
R28 R29 = RK73G1ETTP1001D: RES 1K OHM 0.5% 1/10W 0402; Manufacturer: KOA Speer Electronics, Inc.; Power (Watts): 0.1W, 1/10W; Temperature Coefficient: ±50ppm/°C
R30 = CRCW04021K00FKTD: RES SMD 1K OHM 1% 1/16W 0402; Manufacturer: Vishay Dale; Power (Watts): 0.063W, 1/16W; Temperature Coefficient: ±100ppm/°C
R31 = ERJ-U02F1100X: RES 110 OHM 1% 1/10W 0402 SMD; Manufacturer: Panasonic Electronic Components; Power (Watts): 0.1W, 1/10W; Temperature Coefficient: ±200ppm/°C
R32 R33 = TNPW04021K00BYEP: RES 1K OHM 0.1% 1/16W 0402; Manufacturer: Vishay Dale; Power (Watts): 0.063W, 1/16W; Temperature Coefficient: ±10ppm/°C
R36 = RMEF0402FT1K00: RES 1K OHM 1% 1/16W 0402; Manufacturer: Stackpole Electronics Inc; Power (Watts): 0.063W, 1/16W; Ratings: 7C1 RoHS w/out Exemption (100% Pb-Free), AEC-Q200; Temperature Coefficient: ±100ppm/°C
U5 U6 = TP4056: Complete single cell Li-Ion battery with a constant current / constant voltage linear charger; MF: NanJing Top Power ASIC Corp.
U7 U8 = DW01A: One Cell Lithium-ion/Polymer Battery Protection IC; MF: Fortune Semiconductor
U10 = USBLC6-2SC6: 17V Clamp 5A (8/20Âµs) Ipp Tvs Diode Surface Mount SOT-23-6; MF: STMicroelectronics

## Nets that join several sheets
+5: MAIN_TX (5 pins), Audio (5 pins), Power_2 (11 pins), USB_C (D6.2)
+8.4: MAIN_TX (R7.2), Power_2 (5 pins)
GND: MAIN_TX (43 pins), Audio (11 pins), Power_2 (17 pins), USB_C (30 pins)
VCCNRF: MAIN_TX (C25.1 JP2.4), Power_2 (C33.2 R24.2 U4.2)
VDD1: MAIN_TX (19 pins), Audio (6 pins), Power_2 (C28.2 R23.2 U3.2)
Audio_PWM: MAIN_TX (U1.92), Audio (R8.2)
CLK_SD: MAIN_TX (U1.78), Audio (P2.5)
CS_SD: MAIN_TX (U1.81), Audio (P2.2 R18.1)
MISO_SD: MAIN_TX (U1.79), Audio (P2.7 R12.1)
MOSI_SD: MAIN_TX (U1.80), Audio (P2.3 R11.1)
USB_DM: MAIN_TX (U1.70), USB_C (U10.6)
USB_DP: MAIN_TX (U1.71), USB_C (U10.4)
